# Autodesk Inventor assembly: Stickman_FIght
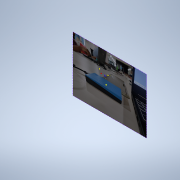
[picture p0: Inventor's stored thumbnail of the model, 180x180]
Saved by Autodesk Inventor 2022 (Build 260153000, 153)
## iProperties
Created: 2022-02
Part Number: Stickman_FIght
Document SubType Name: Assembly
Designer: joshw
Author: joshw
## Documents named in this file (5)
- D:\Fab_Labs\Week_3\Inventor_3D\Fun\Stickman_FIght.iam
- D:\Fab_Labs\Week_3\Inventor_3D\Fun\Body1.ipt
- D:\Fab_Labs\Week_3\Inventor_3D\Fun\body parts.ipt
- D:\Fab_Labs\Week_3\Inventor_3D\Fun\SXS.ipt
- D:\Fab_Labs\Week_3\Inventor_3D\Fun\gLOW_rED.ipt
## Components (23 placed, 4 different names)
1. Body1:1 — Rotational:1, Rotational:4, Rotational:6, Rotational:8
2. body parts:1 — Rotational:1, Rotational:2
3. body parts:2 — Rotational:2, Mate:5, Mate:6, Mate:7
4. body parts:4 — Mate:2, Mate:3, Mate:4
5. body parts:5 — Rotational:4
6. SXS:1 — Mate:1, Flush:3
7. body parts:6 — Rotational:6
8. body parts:7
9. body parts:8 — Rotational:8
10. body parts:9
11. Body1:2
12. body parts:10
13. body parts:11 — Mate:8, Mate:9, Mate:10
14. body parts:12 — Mate:11, Mate:12, Mate:13
15. body parts:13
16. body parts:14
17. body parts:15
18. body parts:16
19. body parts:17
20. gLOW_rED:1 — Mate:2, Mate:3, Mate:4
21. gLOW_rED:2 — Mate:5, Mate:6, Mate:7
22. gLOW_rED:3 — Mate:8, Mate:9, Mate:10
23. gLOW_rED:4 — Mate:11, Mate:12, Mate:13
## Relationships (19: Mate 13, RevoluteJoint 5, Flush 1)
- Rotational:1 [RevoluteJoint]: Body1:1 ↔ body parts:1
- Rotational:2 [RevoluteJoint]: body parts:1 ↔ body parts:2
- Rotational:4 [RevoluteJoint]: Body1:1 ↔ body parts:5
- Mate:1: SXS:1
- Flush:3: SXS:1
- Rotational:6 [RevoluteJoint]: Body1:1 ↔ body parts:6
- Rotational:8 [RevoluteJoint]: Body1:1 ↔ body parts:8
- Mate:2: body parts:4 ↔ gLOW_rED:1
- Mate:3: body parts:4 ↔ gLOW_rED:1
- Mate:4: body parts:4 ↔ gLOW_rED:1
- Mate:5: body parts:2 ↔ gLOW_rED:2
- Mate:6: body parts:2 ↔ gLOW_rED:2
- Mate:7: body parts:2 ↔ gLOW_rED:2
- Mate:8: body parts:11 ↔ gLOW_rED:3
- Mate:9: body parts:11 ↔ gLOW_rED:3
- Mate:10: body parts:11 ↔ gLOW_rED:3
- Mate:11: body parts:12 ↔ gLOW_rED:4
- Mate:12: body parts:12 ↔ gLOW_rED:4
- Mate:13: body parts:12 ↔ gLOW_rED:4
## Named parameters: d13_d11 = 0, d14_d12 = 0.01037 mm, d19_d11 = 0, d20_d12 = -8.33797 mm, d23_d19_d11 = 0, d24_d20_d12 = -10.40137 mm, d27_d9 = 0, d28_d10 = -7.64029 mm, d29_d11 = 0, d30_d12 = -17.06109 mm, d31_d13_d11 = 0, d32_d14_d12 = 28.02276 mm, d33_d15 = 0, d34_d16 = 7.33661 mm, d35_d19_d11 = 0, d36_d20_d12 = 6.40445 mm, d37_d21 = 0, d38_d22 = 7.04976 mm, d39_d23_d19_d11 = 0, d40_d24_d20_d12 = -0.22384 mm, d41_d25 = 0, d42_d26 = 2.7337 mm
